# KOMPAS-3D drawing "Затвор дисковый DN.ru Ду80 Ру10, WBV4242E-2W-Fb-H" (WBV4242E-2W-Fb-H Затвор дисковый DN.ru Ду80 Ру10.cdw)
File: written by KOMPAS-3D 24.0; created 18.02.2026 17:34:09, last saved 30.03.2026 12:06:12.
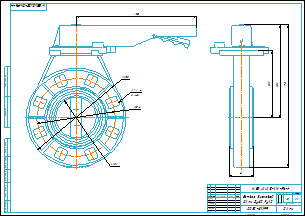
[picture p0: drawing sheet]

Document properties: Автор: R2D2; Форматы листов документа: A2; Полное имя файла: WBV4242E-2W-Fb-H Затвор дисковый DN.ru Ду80 Ру10.m3d; Масса: 1.8; Наименование: Затвор дисковый DN.ru Ду80 Ру10; Количество листов документа: 1; Примечание: D050-81199

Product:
- Component [assembly]: Сборка1  | qty 1  | Масса: 6.148468; Автор: R2D2; source file: исходные материалы\dn80_3d_step.a3d
- Part/product: Затвор дисковый DN.ru Ду80 Ру10  | designation WBV4242E-2W-Fb-H
    Масса: 1.8
    Раздел спецификации: Прочие изделия
    Примечание: D050-81199

Views: Проекционный вид 2
Referenced files in E:\Работа\Зайцев\WBV4242E-2W-Fb-ISO Затвор дисковый DN.ru Ду50-200 Ру10\DN80\: WBV4242E-2W-Fb-ISO Затвор дисковый DN.ru Ду80 Ру10.m3d
Referenced files in E:\Работа\Зайцев\Для компаса\: чертеж DN.ru А3.cdt
Referenced files in E:\Работа\Зайцев\WBV4242E-2W-Fb-H Затвор дисковый DN.ru Ду50-200 Ру10\DN80\исходные материалы\: Деталь1 Деталь1.m3d, Деталь2 Деталь2.m3d, dn80_3d_step.a3d
Referenced files in E:\Работа\Зайцев\WBV4242E-2W-Fb-H Затвор дисковый DN.ru Ду50-200 Ру10\DN80\: WBV4242E-2W-Fb-H Затвор дисковый DN.ru Ду80 Ру10.m3d
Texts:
  WBV4242E-2W-Fb-H
  чертеж DN.ru А3.cdt
  Затвор дисковый
  DN.ru Ду80 Ру10
  Твердое тело1
  Деталь1
  Деталь1 Деталь1
  Деталь2
  Деталь2 Деталь2
  Сборка1
  Сборка1 Сборка1
  Затвор дисковый DN.ru Ду80 Ру10
  WBV4242E-2W-Fb-H Затвор дисковый DN.ru Ду80 Ру10
Dimensions and other numbers on the sheet: 0; 3; 4; 48; 131; 278; 181; 1:1; 1; 2; 1,8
